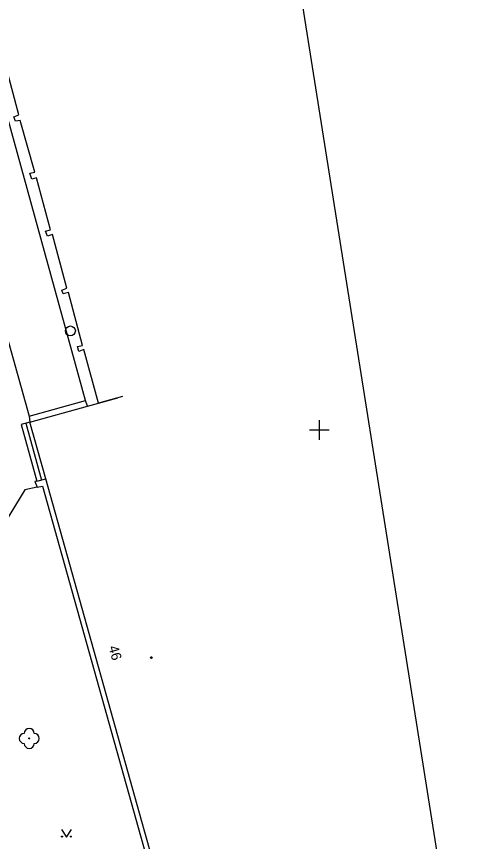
# Model space of a CAD drawing. Extents: x -599098 to -598820, y -1159597 to -1158744.
# Drawn here: x -598930.4 to -598885.5, y -1159141.4 to -1159058.4 of the extents above; entities that cross this region are included whole.
import ezdxf

# ---------------------------------------------------------------- set-up
doc = ezdxf.new("R2010")
doc.units = 0
for name, color, linetype in [('budovy', 7, 'Continuous'), ('druh pozemku stromy', 7, 'Continuous'), ('hektometrická síť', 7, 'Continuous'), ('kresba', 7, 'Continuous'), ('mapový rám legenda', 7, 'Continuous'), ('popisy budov', 7, 'Continuous'), ('značky IS', 7, 'Continuous')]:
    doc.layers.add(name, color=color, linetype=linetype)

msp = doc.modelspace()

# ---------------------------------------------------------------- linework, layer by layer
at = {"layer": 'budovy'}
for points in [[(-598928.61, -1159074.06), (-598930.07, -1159068.88), (-598930.55, -1159068.94), (-598930.73, -1159068.5), (-598930.21, -1159068.32), (-598931.62, -1159063.01), (-598932.14, -1159063.2), (-598932.32, -1159062.67), (-598931.82, -1159062.55), (-598933.28, -1159057.34)], [(-598919.799, -1159096.647), (-598922.21, -1159097.31), (-598923.66, -1159091.91), (-598924.19, -1159092.1), (-598924.3, -1159091.61), (-598923.81, -1159091.5), (-598925.23, -1159086.19), (-598925.75, -1159086.32), (-598925.88, -1159085.93), (-598925.37, -1159085.74), (-598926.84, -1159080.34), (-598927.33, -1159080.52), (-598927.53, -1159080.02), (-598927.02, -1159079.87), (-598928.45, -1159074.63), (-598928.92, -1159074.79), (-598929.12, -1159074.17), (-598928.61, -1159074.06)], [(-598911.988, -1159150.821), (-598914.42, -1159151.56), (-598927.48, -1159104.91), (-598929.09, -1159099.2), (-598923.3, -1159097.62), (-598922.21, -1159097.31), (-598920.254, -1159096.773)]]:
    msp.add_lwpolyline(points, dxfattribs=at)
for radius in [0.09, 0.0398]:
    msp.add_circle((-598916.89, -1159122.89), radius, dxfattribs=at)
at = {"layer": 'druh pozemku stromy'}
msp.add_lwpolyline([(-598925.92, -1159140.19), (-598925.42, -1159140.94), (-598924.92, -1159140.19)], dxfattribs=at)
for centre in [(-598929.17, -1159131.02), (-598925.87, -1159140.89), (-598924.971, -1159140.89)]:
    msp.add_circle(centre, 0.05, dxfattribs=at)
for centre, start, end in [((-598929.67, -1159131.02), 90, 270), ((-598929.17, -1159130.52), 0, 180), ((-598928.67, -1159131.02), 270, 90), ((-598929.17, -1159131.52), 180, 0)]:
    msp.add_arc(centre, 0.5, start, end, dxfattribs=at)
at = {"layer": 'hektometrická síť'}
for p, q in [((-598900, -1159101), (-598900, -1159099)), ((-598901, -1159100), (-598899, -1159100))]:
    msp.add_line(p, q, dxfattribs=at)
at = {"layer": 'kresba'}
for p, q in [((-598929.18, -1159098.6), (-598923.52, -1159097.05)), ((-598929.52, -1159099.32), (-598927.94, -1159105.03))]:
    msp.add_line(p, q, dxfattribs=at)
for points in [[(-598923.3, -1159097.62), (-598923.52, -1159097.05), (-598939.2, -1159040.12)], [(-598940.18, -1159040.43), (-598942.4, -1159041.16), (-598944.28, -1159043.88), (-598939.55, -1159061.52), (-598929.18, -1159098.6)], [(-598929.18, -1159098.6), (-598929.09, -1159099.2)], [(-598929.09, -1159099.2), (-598929.96, -1159099.44), (-598928.39, -1159105.15), (-598927.48, -1159104.91)], [(-598928.39, -1159105.15), (-598928.59, -1159105.17), (-598928.37, -1159105.76)], [(-598928.37, -1159105.76), (-598927.84, -1159105.64), (-598914.74, -1159152.41), (-598912.34, -1159151.78)], [(-598928.37, -1159105.76), (-598929.62, -1159106.03), (-598932.56, -1159110.82)]]:
    msp.add_lwpolyline(points, dxfattribs=at)
at = {"layer": 'mapový rám legenda'}
msp.add_line((-598885.509, -1159159.218), (-598901.935, -1159055.511), dxfattribs=at)
at = {"layer": 'značky IS'}
msp.add_circle((-598925.03, -1159090.04), 0.5, dxfattribs=at)

# ---------------------------------------------------------------- texts
at = {"layer": 'popisy budov'}
msp.add_text(' 46 ', height=1, rotation=285.94, dxfattribs=at).set_placement((-598921.31, -1159121.47))

doc.saveas('drawing.dxf')
